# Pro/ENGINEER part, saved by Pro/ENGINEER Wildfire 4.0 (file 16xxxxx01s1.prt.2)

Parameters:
  HERSTELLER = "Hersteller"
  NB = "16XXXXX01S-1"
  NN = "16-S1"
  NT = "16 Series - Swivel - Top Plate"
  NBSYN = "$PN."
  LINA = "16XXXXX01S-1"
  PN = "16XXXXX01S-1"
  KT = "DUMMY"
